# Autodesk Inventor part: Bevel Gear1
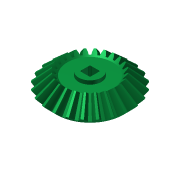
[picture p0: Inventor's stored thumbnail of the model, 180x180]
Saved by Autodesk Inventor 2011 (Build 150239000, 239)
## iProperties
Created: 2010-04
Part Number: Bevel Gear1
Material: ABS Plastic
Document SubType Name: Modeling
Designer: Phil
Categories: <?xml version="1.0" encoding="UTF-16"?> <MemberInstance><Categories><FamilyTemplate><FamilyTemplateParameter ValueType="xs:double" Id="1" ObjectReferenceKey="da
Mass: 1.68349 g
Surface Area: 21.9898 cm^2
Volume: 1.58819 cm^3
Density: 1.06 g/cm^3
CustomPartVersion: 1
Author: Phil
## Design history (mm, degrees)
node "Top Point"
node "Mesh Plane2"
sketch "Teeth Body Sketch"
  geometry: L1 (0, 0)-(11.802, -13.598); L2 (11.802, -13.598)-(13.448, -11.952); L3 (13.448, -11.952)-(0, 0); L4 (12.7, -12.7)-(0, 0); L5 (7.629, -8.79)-(8.694, -7.726); L6 (11.802, -13.598)-(7.629, -8.79); L7 (13.448, -11.952)-(8.694, -7.726); L8 (0, -39.387)-(0, 6.564) reference; L9 (0, -12.7)-(13.448, -12.7)
  constraints: 16 end point, 4 point on line, 3 perpendicular, 2 collinear, 1 horizontal alignment, 1 vertical alignment
  dimensions: "d0" = 25.4 diameter of L4.start L8 (= da_de); "d1" = 23.60395 diameter of L1.end L8 (= da_dfe); "d2" = 26.89671 diameter of L2.end L8 (= da_dae); "d3" = 6.35 distance between parallel lines of L2 L5 (= da_b); "d4" = 11.95165 vertical distance of L2.end L1.start (= da_ve)
revolve "Teeth Body" sketch "Teeth Body Sketch" stored, may be unused: angle "d5" = 90 deg
node "Start Point"
node "Tooth Plane"
sketch "Start Sketch"
  geometry: L1 (0, -23.505)-(0, 10.645) reference; L2 (-0.4, -1.549)-(0.4, -1.549); A1 r 6.505 centre (-6.831, -2.533) between (-0.4, -1.549) and (-1.864, 1.669); A2 r 6.505 centre (6.831, -2.533) between (1.864, 1.669) and (0.4, -1.549); A3 r 19.717 centre (0, -17.961) between (1.864, 1.669) and (-1.864, 1.669); 1 further point
  constraints: 6 point on circle, 3 centre point, 3 symmetric about line, 2 end point, 1 coincident, 1 perpendicular, 1 other
  dimensions: "d7" = 6.50483 radius of A1 (= fd_rr); "d8" = 6.83059 horizontal distance of point (0, -17.961) A1.centre (= fd_x); "d9" = 15.42797 vertical distance of point (0, -17.961) A1.centre (= fd_y); "d57" = 19.71735 radius of A3 (= 0.5 x fd_dva + 0.3 x da_he); "d58" = 16.41111 distance from line of A3.centre L2 (= 0.5 x fd_dva - 1.12 x da_he)
node "End Point"
  node "End Plane"
sketch "3D Sketch Right"
  node "Helical Curve Right" dims "d65" = 127.62048 (computed from da_dm, da_delta, da_beta), "d66" = 31.5, "d67" = 25.4 (= da_de), "d68" = -45 deg (= -da_delta), "d69" = 4.57245 (computed from fd_loft, da_delta)
node "End Plane Right"
sketch "End Sketch Right"
  geometry: L1 (0, -18.196)-(0, 9.82) reference; L2 (-0.257, -0.975)-(0.257, -0.975); A1 r 4.169 centre (-4.378, -1.605) between (-0.257, -0.975) and (-1.195, 1.087); A2 r 4.169 centre (4.378, -1.605) between (1.195, 1.087) and (0.257, -0.975); A3 r 12.638 centre (0, -11.494) between (1.195, 1.087) and (-1.195, 1.087); 1 further point
  constraints: 6 point on circle, 3 centre point, 3 symmetric about line, 2 end point, 1 coincident, 1 perpendicular, 1 other
  dimensions: "d70" = 4.37817 horizontal distance of A3.centre A1.centre (computed from fd_x, fd_ratio); "d71" = 9.88879 vertical distance of point (0, -11.494) A1.centre (computed from fd_y, fd_ratio); "d72" = 4.16937 radius of A1 (computed from fd_rr, fd_ratio); "d73" = 10.51895 distance from line of point (0, -11.494) L2 (computed from d58, fd_ratio); "d74" = 12.63812 radius of A3 (computed from d57, fd_ratio)
feature "Loft Right" sketch "End Sketch Right" dims "d75" = 0, "d76" = 90 deg, "d77" = 0, "d78" = 90 deg, "d79" = 0, "d80" = 90 deg, "d85" = 20, "da_teethtype" = 0 [user parameter]
sketch "3D Sketch Left"
  node "Helical Curve Left" dims "d26" = 127.62048 (computed from da_dm, da_delta, da_beta), "d27" = 4.57245 (computed from fd_loft, da_delta), "d28" = 25.4 (= da_de), "d29" = -45 deg (= -da_delta)
node "End Plane Left"
sketch "End Sketch Left" dims "d56" = 6.1486 (derived)
  geometry: L1 (0, -31.428)-(0, 14.43) reference; L2 (-0.257, -0.973)-(0.257, -0.973); A1 r 4.169 centre (-4.378, -1.603) between (-0.257, -0.973) and (-1.195, 1.09); A2 r 4.169 centre (4.378, -1.603) between (1.195, 1.09) and (0.257, -0.973); A3 r 12.638 centre (0, -11.492) between (1.195, 1.09) and (-1.195, 1.09); 2 further points; 1 other entity
  constraints: 6 point on circle, 3 centre point, 3 symmetric about line, 2 end point, 1 coincident, 2 other
  dimensions: "d30" = 4.16937 radius of A1 (computed from fd_rr, fd_ratio); "d31" = 4.37817 horizontal distance of point (0, -11.492) A1.centre (computed from fd_x, fd_ratio); "d32" = 9.88879 vertical distance of A1.centre point (0, -11.492) (computed from fd_y, fd_ratio); "d61" = 12.63812 radius of A3 (computed from d57, fd_ratio); "d62" = 10.51895 distance from line of point (0, -11.492) L2 (computed from d58, fd_ratio)
feature "Loft Left" sketch "End Sketch Left" dims "d35" = 0, "d37" = 0, "d39" = 0, "d40" = 90 deg, "d63" = 90 deg, "d64" = 90 deg, "d84" = 10, "da_teethtype" = 0 [user parameter]
sketch "Body Sketch"
  geometry: L1 (0, -35.038)-(0, -19.531) reference; L2 (11.802, -13.598)-(7.629, -8.79) reference; L3 (7.629, -8.79)-(0, -8.79); L4 (11.802, -13.598)-(0, -13.598)
  constraints: 4 end point, 2 perpendicular, 2 point on line
revolve "Fix Body" sketch "Body Sketch" stored, may be unused: angle "d46" = 90 deg
sketch "Sketch6"
  geometry: L1 (12.7, -12.7)-(0, 0) reference; L2 (0, -37.8)-(0, 6.3) reference
feature "Pitch Diameter" sketch "Sketch6" dims angle "d47" = 90 deg
sketch "Sketch8"
  geometry: A1 r 7.629 centre (0, 0) between (0.287, 7.624) and (-0.287, 7.624) reference; A2 r 7.629 centre (0, 0) between (-0.287, 7.624) and (-1.696, 7.438) reference; A3 r 7.629 centre (0, 0) between (-1.696, 7.438) and (-2.25, 7.29) reference; A4 r 7.629 centre (0, 0) between (-2.25, 7.29) and (-3.564, 6.746) reference; A5 r 7.629 centre (0, 0) between (-3.564, 6.746) and (-4.06, 6.459) reference; A6 r 7.629 centre (0, 0) between (-4.06, 6.459) and (-5.188, 5.594) reference; A7 r 7.629 centre (0, 0) between (-5.188, 5.594) and (-5.594, 5.188) reference; A8 r 7.629 centre (0, 0) between (-5.594, 5.188) and (-6.459, 4.06) reference; A9 r 7.629 centre (0, 0) between (-6.459, 4.06) and (-6.746, 3.564) reference; A10 r 7.629 centre (0, 0) between (-6.746, 3.564) and (-7.29, 2.25) reference; A11 r 7.629 centre (0, 0) between (-7.29, 2.25) and (-7.438, 1.696) reference; A12 r 7.629 centre (0, 0) between (-7.438, 1.696) and (-7.624, 0.287) reference; A13 r 7.629 centre (0, 0) between (-7.624, 0.287) and (-7.624, -0.287) reference; A14 r 7.629 centre (0, 0) between (-7.624, -0.287) and (-7.438, -1.696) reference; A15 r 7.629 centre (0, 0) between (-7.438, -1.696) and (-7.29, -2.25) reference; A16 r 7.629 centre (0, 0) between (-7.29, -2.25) and (-6.746, -3.564) reference; A17 r 7.629 centre (0, 0) between (-6.746, -3.564) and (-6.459, -4.06) reference; A18 r 7.629 centre (0, 0) between (-6.459, -4.06) and (-5.594, -5.188) reference; A19 r 7.629 centre (0, 0) between (-5.594, -5.188) and (-5.188, -5.594) reference; A20 r 7.629 centre (0, 0) between (-5.188, -5.594) and (-4.06, -6.459) reference; A21 r 7.629 centre (0, 0) between (-4.06, -6.459) and (-3.564, -6.746) reference; A22 r 7.629 centre (0, 0) between (-3.564, -6.746) and (-2.25, -7.29) reference; A23 r 7.629 centre (0, 0) between (-2.25, -7.29) and (-1.696, -7.438) reference; A24 r 7.629 centre (0, 0) between (-1.696, -7.438) and (-0.287, -7.624) reference; A25 r 7.629 centre (0, 0) between (-0.287, -7.624) and (0.287, -7.624) reference; A26 r 7.629 centre (0, 0) between (0.287, -7.624) and (1.696, -7.438) reference; A27 r 7.629 centre (0, 0) between (1.696, -7.438) and (2.25, -7.29) reference; A28 r 7.629 centre (0, 0) between (2.25, -7.29) and (3.564, -6.746) reference; A29 r 7.629 centre (0, 0) between (3.564, -6.746) and (4.06, -6.459) reference; A30 r 7.629 centre (0, 0) between (4.06, -6.459) and (5.188, -5.594) reference; A31 r 7.629 centre (0, 0) between (5.188, -5.594) and (5.594, -5.188) reference; A32 r 7.629 centre (0, 0) between (5.594, -5.188) and (6.459, -4.06) reference; A33 r 7.629 centre (0, 0) between (6.459, -4.06) and (6.746, -3.564) reference; A34 r 7.629 centre (0, 0) between (6.746, -3.564) and (7.29, -2.25) reference; A35 r 7.629 centre (0, 0) between (7.29, -2.25) and (7.438, -1.696) reference; A36 r 7.629 centre (0, 0) between (7.438, -1.696) and (7.624, -0.287) reference; A37 r 7.629 centre (0, 0) between (7.624, -0.287) and (7.624, 0.287) reference; A38 r 7.629 centre (0, 0) between (7.624, 0.287) and (7.438, 1.696) reference; A39 r 7.629 centre (0, 0) between (7.438, 1.696) and (7.29, 2.25) reference; A40 r 7.629 centre (0, 0) between (7.29, 2.25) and (6.746, 3.564) reference; A41 r 7.629 centre (0, 0) between (6.746, 3.564) and (6.459, 4.06) reference; A42 r 7.629 centre (0, 0) between (6.459, 4.06) and (5.594, 5.188) reference; A43 r 7.629 centre (0, 0) between (5.594, 5.188) and (5.188, 5.594) reference; A44 r 7.629 centre (0, 0) between (5.188, 5.594) and (4.06, 6.459) reference; A45 r 7.629 centre (0, 0) between (4.06, 6.459) and (3.564, 6.746) reference; A46 r 7.629 centre (0, 0) between (3.564, 6.746) and (2.25, 7.29) reference; A47 r 7.629 centre (0, 0) between (2.25, 7.29) and (1.696, 7.438) reference; A48 r 7.629 centre (0, 0) between (1.696, 7.438) and (0.287, 7.624) reference
extrude "Extrusion1" cut sketch "Sketch8" distance "d90" = 0.3556; taper "d91" = -45 deg
sketch "Sketch9"
  geometry: A1 r 11.802 centre (0, 0) between (0.448, 11.793) and (-0.448, 11.793) reference; A2 r 11.802 centre (0, 0) between (-0.448, 11.793) and (-2.62, 11.508) reference; A3 r 11.802 centre (0, 0) between (-2.62, 11.508) and (-3.485, 11.276) reference; A4 r 11.802 centre (0, 0) between (-3.485, 11.276) and (-5.509, 10.437) reference; A5 r 11.802 centre (0, 0) between (-5.509, 10.437) and (-6.285, 9.989) reference; A6 r 11.802 centre (0, 0) between (-6.285, 9.989) and (-8.022, 8.656) reference; A7 r 11.802 centre (0, 0) between (-8.022, 8.656) and (-8.656, 8.022) reference; A8 r 11.802 centre (0, 0) between (-8.656, 8.022) and (-9.989, 6.285) reference; A9 r 11.802 centre (0, 0) between (-9.989, 6.285) and (-10.437, 5.509) reference; A10 r 11.802 centre (0, 0) between (-10.437, 5.509) and (-11.276, 3.485) reference; A11 r 11.802 centre (0, 0) between (-11.276, 3.485) and (-11.508, 2.62) reference; A12 r 11.802 centre (0, 0) between (-11.508, 2.62) and (-11.793, 0.448) reference; A13 r 11.802 centre (0, 0) between (-11.793, 0.448) and (-11.793, -0.448) reference; A14 r 11.802 centre (0, 0) between (-11.793, -0.448) and (-11.508, -2.62) reference; A15 r 11.802 centre (0, 0) between (-11.508, -2.62) and (-11.276, -3.485) reference; A16 r 11.802 centre (0, 0) between (-11.276, -3.485) and (-10.437, -5.509) reference; A17 r 11.802 centre (0, 0) between (-10.437, -5.509) and (-9.989, -6.285) reference; A18 r 11.802 centre (0, 0) between (-9.989, -6.285) and (-8.656, -8.022) reference; A19 r 11.802 centre (0, 0) between (-8.656, -8.022) and (-8.022, -8.656) reference; A20 r 11.802 centre (0, 0) between (-8.022, -8.656) and (-6.285, -9.989) reference; A21 r 11.802 centre (0, 0) between (-6.285, -9.989) and (-5.509, -10.437) reference; A22 r 11.802 centre (0, 0) between (-5.509, -10.437) and (-3.485, -11.276) reference; A23 r 11.802 centre (0, 0) between (-3.485, -11.276) and (-2.62, -11.508) reference; A24 r 11.802 centre (0, 0) between (-2.62, -11.508) and (-0.448, -11.793) reference; A25 r 11.802 centre (0, 0) between (-0.448, -11.793) and (0.448, -11.793) reference; A26 r 11.802 centre (0, 0) between (0.448, -11.793) and (2.62, -11.508) reference; A27 r 11.802 centre (0, 0) between (2.62, -11.508) and (3.485, -11.276) reference; A28 r 11.802 centre (0, 0) between (3.485, -11.276) and (5.509, -10.437) reference; A29 r 11.802 centre (0, 0) between (5.509, -10.437) and (6.285, -9.989) reference; A30 r 11.802 centre (0, 0) between (6.285, -9.989) and (8.022, -8.656) reference; A31 r 11.802 centre (0, 0) between (8.022, -8.656) and (8.656, -8.022) reference; A32 r 11.802 centre (0, 0) between (8.656, -8.022) and (9.989, -6.285) reference; A33 r 11.802 centre (0, 0) between (9.989, -6.285) and (10.437, -5.509) reference; A34 r 11.802 centre (0, 0) between (10.437, -5.509) and (11.276, -3.485) reference; A35 r 11.802 centre (0, 0) between (11.276, -3.485) and (11.508, -2.62) reference; A36 r 11.802 centre (0, 0) between (11.508, -2.62) and (11.793, -0.448) reference; A37 r 11.802 centre (0, 0) between (11.793, -0.448) and (11.793, 0.448) reference; A38 r 11.802 centre (0, 0) between (11.793, 0.448) and (11.508, 2.62) reference; A39 r 11.802 centre (0, 0) between (11.508, 2.62) and (11.276, 3.485) reference; A40 r 11.802 centre (0, 0) between (11.276, 3.485) and (10.437, 5.509) reference; A41 r 11.802 centre (0, 0) between (10.437, 5.509) and (9.989, 6.285) reference; A42 r 11.802 centre (0, 0) between (9.989, 6.285) and (8.656, 8.022) reference; A43 r 11.802 centre (0, 0) between (8.656, 8.022) and (8.022, 8.656) reference; A44 r 11.802 centre (0, 0) between (8.022, 8.656) and (6.285, 9.989) reference; A45 r 11.802 centre (0, 0) between (6.285, 9.989) and (5.509, 10.437) reference; A46 r 11.802 centre (0, 0) between (5.509, 10.437) and (3.485, 11.276) reference; A47 r 11.802 centre (0, 0) between (3.485, 11.276) and (2.62, 11.508) reference; A48 r 11.802 centre (0, 0) between (2.62, 11.508) and (0.448, 11.793) reference
extrude "Extrusion2" join sketch "Sketch9" distance "d92" = 1.1176; taper "d93" = -45 deg
sketch "Sketch10"
  geometry: C1 r 7.274 at (0, 0) reference; C2 r 3.632 at (0, 0)
  constraints: 1 centre point, 1 coincident
  dimensions: "d94" = 7.2644 diameter of C2
extrude "Extrusion3" join sketch "Sketch10" distance "d95" = 9.525; taper "d96" = 0 deg
extrude "Extrusion4" join sketch "Sketch10" distance "d97" = 1.1938; taper "d98" = 0 deg
sketch "Sketch11"
  geometry: L1 (1.612, 0.952)-(1.558, 1.007); L2 (1.558, 1.025)-(1.612, 1.079); L3 (1.612, 1.104)-(1.612, 1.079); L4 (1.558, 1.177)-(1.612, 1.231); L5 (1.612, 1.362)-(1.612, 1.231); L6 (1.232, 1.612)-(1.177, 1.558); L7 (1.159, 1.558)-(1.105, 1.612); L8 (1.079, 1.612)-(1.105, 1.612); L9 (1.232, 1.612)-(1.362, 1.612); L10 (1.612, 0.952)-(1.612, -0.952); L11 (1.558, -1.007)-(1.612, -0.952); L12 (1.612, 1.104)-(1.558, 1.159); L13 (1.079, 1.612)-(1.025, 1.558); L14 (-1.362, 1.612)-(-1.231, 1.612); L15 (-1.177, 1.558)-(-1.231, 1.612); L16 (1.007, 1.558)-(0.952, 1.612); L17 (-0.952, 1.613)-(0.952, 1.612); L18 (-0.952, 1.613)-(-1.007, 1.558); L19 (-1.024, 1.558)-(-1.079, 1.612); L20 (-1.104, 1.613)-(-1.079, 1.612); L21 (-1.104, 1.613)-(-1.159, 1.558); L22 (1.613, -1.079)-(1.558, -1.024); L23 (1.613, -1.079)-(1.612, -1.105); L24 (1.558, -1.159)-(1.612, -1.105); L25 (1.613, -1.231)-(1.558, -1.177); L26 (1.613, -1.231)-(1.612, -1.362); L27 (1.362, -1.612)-(1.231, -1.612); L28 (1.177, -1.558)-(1.231, -1.612); L29 (1.104, -1.613)-(1.079, -1.612); L30 (1.024, -1.558)-(1.079, -1.612); L31 (0.952, -1.613)-(1.007, -1.558); L32 (0.952, -1.613)-(-0.952, -1.612); L33 (1.104, -1.613)-(1.159, -1.558); L34 (-1.007, -1.558)-(-0.952, -1.612); L35 (-1.079, -1.612)-(-1.025, -1.558); L36 (-1.079, -1.612)-(-1.105, -1.612); L37 (-1.159, -1.558)-(-1.105, -1.612); L38 (-1.232, -1.612)-(-1.177, -1.558); L39 (-1.612, -0.952)-(-1.558, -1.007); L40 (-1.558, -1.025)-(-1.612, -1.079); L41 (-1.612, -1.104)-(-1.612, -1.079); L42 (-1.612, -1.104)-(-1.558, -1.159); L43 (-1.558, -1.177)-(-1.612, -1.231); L44 (-1.612, -1.362)-(-1.612, -1.231); L45 (-1.232, -1.612)-(-1.362, -1.612); L46 (-1.612, -0.952)-(-1.612, 0.952); L47 (-1.558, 1.007)-(-1.612, 0.952); L48 (-1.613, 1.079)-(-1.558, 1.024); L49 (-1.613, 1.079)-(-1.612, 1.105); L50 (-1.558, 1.159)-(-1.612, 1.105); L51 (-1.613, 1.231)-(-1.558, 1.177); L52 (-1.613, 1.231)-(-1.612, 1.362); A1 r 0.013 centre (1.567, 1.016) between (1.558, 1.025) and (1.558, 1.007); A2 r 0.013 centre (1.567, 1.168) between (1.558, 1.177) and (1.558, 1.159); A3 r 0.25 centre (1.362, 1.362) between (1.612, 1.362) and (1.362, 1.612); A4 r 0.013 centre (1.168, 1.567) between (1.159, 1.558) and (1.177, 1.558); A5 r 0.012 centre (-1.016, 1.566) between (-1.024, 1.558) and (-1.007, 1.558); A6 r 0.012 centre (-1.168, 1.566) between (-1.177, 1.558) and (-1.159, 1.558); A7 r 0.013 centre (1.016, 1.567) between (1.007, 1.558) and (1.025, 1.558); A8 r 0.012 centre (1.566, -1.016) between (1.558, -1.007) and (1.558, -1.024); A9 r 0.013 centre (1.567, -1.168) between (1.558, -1.159) and (1.558, -1.177); A10 r 0.25 centre (1.362, -1.362) between (1.362, -1.612) and (1.612, -1.362); A11 r 0.012 centre (1.168, -1.566) between (1.177, -1.558) and (1.159, -1.558); A12 r 0.012 centre (1.016, -1.566) between (1.024, -1.558) and (1.007, -1.558); A13 r 0.013 centre (-1.016, -1.567) between (-1.007, -1.558) and (-1.025, -1.558); A14 r 0.013 centre (-1.168, -1.567) between (-1.159, -1.558) and (-1.177, -1.558); A15 r 0.013 centre (-1.567, -1.168) between (-1.558, -1.177) and (-1.558, -1.159); A16 r 0.013 centre (-1.567, -1.016) between (-1.558, -1.025) and (-1.558, -1.007); A17 r 0.25 centre (-1.362, -1.362) between (-1.612, -1.362) and (-1.362, -1.612); A18 r 0.25 centre (-1.362, 1.362) between (-1.362, 1.612) and (-1.612, 1.362); A19 r 0.013 centre (-1.567, 1.168) between (-1.558, 1.159) and (-1.558, 1.177); A20 r 0.012 centre (-1.566, 1.016) between (-1.558, 1.007) and (-1.558, 1.024); 1 further point
  constraints: 104 end point, 40 point on circle, 20 centre point
feature "iFeature2:1" sketch "Sketch11"
sketch "Sketch12"
  geometry: L1 (10.684, -14.716)-(-10.684, -14.716) reference; L2 (-3.632, -14.716)-(-3.632, -18.671) reference; L3 (-10.684, -14.716)-(-7.221, -10.702); L4 (-7.221, -10.702)-(-3.632, -10.702); L5 (-3.632, -10.702)-(-3.632, -14.716); L6 (0, -22.405)-(0, 3.734) reference; 1 further point
  constraints: 6 end point, 2 perpendicular
  dimensions: "d99" = 49.21 deg angle of L1 L3; "d100" = 4.0132 distance between parallel lines of L1 L4
revolve "Revolution3" sketch "Sketch12" stored, may be unused: angle "d101" = 90 deg
sketch "Sketch13"
  geometry: L1 (-3.632, -10.702)-(-3.632, -18.671) reference; L2 (-10.684, -14.716)-(-3.632, -14.687); 1 further point
  constraints: 2 end point, 1 midpoint
feature "Rib1" sketch "Sketch13" dims "d102" = 2.54, "d103" = 1.27, "d104" = 0
pattern_circular "Circular Pattern4" dims angle "d106" = 360 deg
body "Solid1"
feature "Loft" dims "d17" = 0, "d18" = 90 deg, "d19" = 0, "d20" = 90 deg, "d89" = 0, "da_teethtype" = 0 [user parameter]
pattern_circular "Circular Pattern" dims angle "d22" = 360 deg, "d88" = 0, "da_teethtype" = 0 [user parameter]
pattern_circular "Circular Pattern Right" dims angle "d82" = 360 deg, "da_teethtype" = 0 [user parameter]
pattern_circular "Circular Pattern Left" dims angle "d42" = 360 deg, "da_teethtype" = 0 [user parameter]
sketch "End Sketch"
  geometry: L1 (0, -15.359)-(0, 6.983) reference; L2 (-0.257, -0.975)-(0.257, -0.975); A1 r 4.169 centre (-4.378, -1.605) between (-0.257, -0.975) and (-1.195, 1.087); A2 r 4.169 centre (4.378, -1.605) between (1.195, 1.087) and (0.257, -0.975); A3 r 12.638 centre (0, -11.494) between (1.195, 1.087) and (-1.195, 1.087); 1 further point
  constraints: 6 point on circle, 3 centre point, 3 symmetric about line, 2 end point, 1 coincident, 1 other
  dimensions: "d12" = 4.16937 radius of A1 (computed from fd_rr, fd_ratio); "d15" = 4.37817 horizontal distance of A1.centre point (0, -11.494) (computed from fd_x, fd_ratio); "d16" = 9.88879 vertical distance of A1.centre point (0, -11.494) (computed from fd_y, fd_ratio); "d59" = 12.63812 radius of A3 (computed from d57, fd_ratio); "d60" = 10.51895 distance from line of A3.centre L2 (computed from d58, fd_ratio)
body "Srf1"
other parameters: "da_b" = 6.35 [user parameter; used in 2 equation terms], "da_de" = 25.4 [user parameter; used in 4 equation terms], "da_dae" = 26.89671 [user parameter; used in 2 equation terms], "da_dfe" = 23.60395 [user parameter; used in 1 equation term], "da_le" = 17.96051 [user parameter; used in 1 equation term], "da_omega" = 90 deg [user parameter; used in 1 equation term], "da_beta" = 0 [user parameter; used in 2 equation terms], "da_delta" = 45 deg [user parameter; used in 8 equation terms], "da_alpha" = 20 deg [user parameter; used in 2 equation terms], "da_he" = 2.32833 [user parameter; used in 4 equation terms], "da_ve" = 11.95165 [user parameter; used in 1 equation term], "fd_dv" = 35.92102 (computed from da_de, da_delta) [user parameter; used in 1 equation term], "fd_dva" = 38.03769 (computed from da_dae, da_delta) [user parameter; used in 3 equation terms], "fd_dvb" = 33.75472 (computed from fd_dv, da_alpha) [user parameter; used in 2 equation terms], "da_zv" = 339.41125 [user parameter; used in 1 equation term], "fd_loft" = 6.46642 (= da_b + 0.05 x da_he) [user parameter; used in 4 equation terms], "fd_ratio" = 6.40965 (computed from da_le, fd_loft) [user parameter; used in 15 equation terms], "fd_rr" = 6.50483 (computed from fd_dd, fd_dvb) [user parameter; used in 6 equation terms], "fd_angle" = 0.4628 (computed from da_zv) [user parameter; used in 4 equation terms], "fd_x1" = 0.83092 (computed from da_dvw, fd_angle) [user parameter; used in 1 equation term], "fd_y1" = 17.94128 (computed from da_dvw, fd_angle) [user parameter; used in 1 equation term], "fd_x2" = 5.99967 (computed from fd_rr, fd_angle2, fd_angle) [user parameter; used in 1 equation term], "fd_y2" = 2.51331 (computed from fd_rr, fd_angle2, fd_angle) [user parameter; used in 1 equation term], "fd_x" = 6.83059 (= fd_x1 + fd_x2) [user parameter; used in 4 equation terms], "fd_y" = 15.42797 (= fd_y1 - fd_y2) [user parameter; used in 4 equation terms], "fd_angle2" = 3.50419 (computed from fd_dvb, fd_dd, da_alpha) [user parameter; used in 2 equation terms], "fd_dd" = 36.17502 (= fd_dva - 0.8 x da_he) [user parameter; used in 2 equation terms], "da_dvw" = 35.92102 [user parameter; used in 2 equation terms], "d11" = 6.46642 (= fd_loft), "da_dm" = 20.90987 [user parameter; used in 2 equation terms], "da_x" = 0 [user parameter], "da_m" = 1.05833 [user parameter], "d48" = 0, "d49" = 0, "d50" = 90 deg (= da_omega), "d51" = 7.5 deg (computed from da_z), "d52" = 0, "d53" = 0, "d54" = 0
